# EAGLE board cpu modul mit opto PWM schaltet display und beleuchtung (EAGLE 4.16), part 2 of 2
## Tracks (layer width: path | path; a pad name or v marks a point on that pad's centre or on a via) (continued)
N$500  (via drill 0.5 pad 1.27)
  other vias: 50.32,1.9
N$501  (via drill 0.5 pad 1.27)
  other vias: 50.32,3.17
N$502  (via drill 0.5 pad 1.27)
  other vias: 49.05,1.9
N$503  (via drill 0.5 pad 1.27)
  other vias: 50.32,0.63
N$504  (via drill 0.5 pad 1.27)
  other vias: 51.59,1.9
N$506  (via drill 0.5 pad 1.27)
  other vias: 49.05,4.44
N$508  (via drill 0.5 pad 1.27)
  other vias: 33.81,24.76
N$509  (via drill 0.5 pad 1.27)
  other vias: 36.35,24.76
N$526  (via drill 0.5 pad 1.27)
  other vias: 5.87,14.6
N$527  (via drill 0.5 pad 1.27)
  other vias: 54.13,53.97
N$528  (via drill 0.5 pad 1.27)
  other vias: 54.13,55.24
N$529  (via drill 0.5 pad 1.27)
  other vias: 31.27,53.97
N$530  (via drill 0.5 pad 1.27)
  other vias: 31.27,55.24
N$531  (via drill 0.5 pad 1.27)
  other vias: 79.53,53.97
N$532  (via drill 0.5 pad 1.27)
  other vias: 82.07,53.97
N$533  (via drill 0.5 pad 1.27)
  other vias: 84.61,53.97
N$534  (via drill 0.5 pad 0.81)
  other vias: 0.79,57.78
N$535  (via drill 0.5 pad 0.81)
  other vias: 2.06,57.78
N$536  (via drill 0.5 pad 0.81)
  other vias: 3.33,57.78
N$537  (via drill 0.5 pad 0.81)
  other vias: 4.6,57.78
N$538  (via drill 0.5 pad 0.81)
  other vias: 5.87,57.78
N$539  (via drill 0.5 pad 0.81)
  other vias: 7.14,57.78
N$540  (via drill 0.5 pad 0.81)
  other vias: 8.41,57.78
N$541  (via drill 0.5 pad 0.81)
  other vias: 9.68,57.78
N$542  (via drill 0.5 pad 0.81)
  other vias: 10.95,57.78
N$543  (via drill 0.5 pad 0.81)
  other vias: 12.22,57.78
N$544  (via drill 0.5 pad 0.81)
  other vias: 13.49,57.78
N$545  (via drill 0.5 pad 0.81)
  other vias: 14.76,57.78
N$546  (via drill 0.5 pad 0.81)
  other vias: 16.03,57.78
N$547  (via drill 0.5 pad 0.81)
  other vias: 17.3,57.78
N$548  (via drill 0.5 pad 0.81)
  other vias: 18.57,57.78
N$549  (via drill 0.5 pad 0.81)
  other vias: 19.84,57.78
N$550  (via drill 0.5 pad 0.81)
  other vias: 21.11,57.78
N$551  (via drill 0.5 pad 0.81)
  other vias: 22.38,57.78
N$552  (via drill 0.5 pad 0.81)
  other vias: 23.65,57.78
N$553  (via drill 0.5 pad 0.81)
  other vias: 24.92,57.78
N$554  (via drill 0.5 pad 0.81)
  other vias: 26.19,57.78
N$555  (via drill 0.5 pad 0.81)
  other vias: 27.46,57.78
N$556  (via drill 0.5 pad 0.81)
  other vias: 28.73,57.78
N$557  (via drill 0.5 pad 0.81)
  other vias: 30,57.78
N$558  (via drill 0.5 pad 0.81)
  other vias: 31.27,57.78
N$559  (via drill 0.5 pad 0.81)
  other vias: 32.54,57.78
N$560  (via drill 0.5 pad 0.81)
  other vias: 33.81,57.78
N$561  (via drill 0.5 pad 0.81)
  other vias: 35.08,57.78
N$562  (via drill 0.5 pad 0.81)
  other vias: 36.35,57.78
N$563  (via drill 0.5 pad 0.81)
  other vias: 37.62,57.78
N$564  (via drill 0.5 pad 0.81)
  other vias: 40.16,57.78
N$565  (via drill 0.5 pad 0.81)
  other vias: 38.89,57.78
N$566  (via drill 0.5 pad 0.81)
  other vias: 41.43,57.78
N$567  (via drill 0.5 pad 0.81)
  other vias: 42.7,57.78
N$568  (via drill 0.5 pad 0.81)
  other vias: 43.97,57.78
N$569  (via drill 0.5 pad 0.81)
  other vias: 45.24,57.78
N$570  (via drill 0.5 pad 0.81)
  other vias: 46.51,57.78
N$571  (via drill 0.5 pad 0.81)
  other vias: 47.78,57.78
N$572  (via drill 0.5 pad 0.81)
  other vias: 49.05,57.78
N$573  (via drill 0.5 pad 0.81)
  other vias: 51.59,57.78
N$574  (via drill 0.5 pad 0.81)
  other vias: 50.32,57.78
N$575  (via drill 0.5 pad 0.81)
  other vias: 52.86,57.78
N$576  (via drill 0.5 pad 0.81)
  other vias: 54.13,57.78
N$577  (via drill 0.5 pad 0.81)
  other vias: 55.4,57.78
N$578  (via drill 0.5 pad 0.81)
  other vias: 56.67,57.78
N$579  (via drill 0.5 pad 0.81)
  other vias: 57.94,57.78
N$580  (via drill 0.5 pad 0.81)
  other vias: 59.21,57.78
N$581  (via drill 0.5 pad 0.81)
  other vias: 60.48,57.78
N$582  (via drill 0.5 pad 0.81)
  other vias: 61.75,57.78
N$583  (via drill 0.5 pad 0.81)
  other vias: 63.02,57.78
N$584  (via drill 0.5 pad 0.81)
  other vias: 64.29,57.78
N$585  (via drill 0.5 pad 0.81)
  other vias: 65.56,57.78
N$586  (via drill 0.5 pad 0.81)
  other vias: 66.83,57.78
N$587  (via drill 0.5 pad 0.81)
  other vias: 68.1,57.78
N$588  (via drill 0.5 pad 0.81)
  other vias: 69.37,57.78
N$589  (via drill 0.5 pad 0.81)
  other vias: 70.64,57.78
N$590  (via drill 0.5 pad 0.81)
  other vias: 71.91,57.78
N$591  (via drill 0.5 pad 0.81)
  other vias: 73.18,57.78
N$592  (via drill 0.5 pad 0.81)
  other vias: 74.45,57.78
N$593  (via drill 0.5 pad 0.81)
  other vias: 75.72,57.78
N$594  (via drill 0.5 pad 0.81)
  other vias: 76.99,57.78
N$595  (via drill 0.5 pad 0.81)
  other vias: 78.26,57.78
N$596  (via drill 0.5 pad 0.81)
  other vias: 79.53,57.78
N$597  (via drill 0.5 pad 0.81)
  other vias: 80.8,57.78
N$598  (via drill 0.5 pad 0.81)
  other vias: 82.07,57.78
N$599  (via drill 0.5 pad 0.81)
  other vias: 83.34,57.78
N$600  (via drill 0.5 pad 0.81)
  other vias: 84.61,57.78
N$601  (via drill 0.5 pad 0.81)
  other vias: 85.88,57.78
N$602  (via drill 0.5 pad 0.81)
  other vias: 87.15,57.78
N$603  (via drill 0.5 pad 1.27)
  other vias: 84.61,42.54
N$604  (via drill 0.5 pad 1.27)
  other vias: 84.61,45.08
N$605  (via drill 0.5 pad 1.27)
  other vias: 75.72,43.81
N$606  (via drill 0.5 pad 1.68)
  Bottom 0.406: 80.8,20.95 82.07,20.95 v83.34,20.95
N$607
  Bottom 0.406: 30,43.81 31.27,43.81
N$608
  Top 1.016: 56.77,61.7 56.77,66.52 56.57,66.72
N$609
  Top 1.016: 59.42,61.5 59.42,66.65
N$610
  Top 1.016: 62,61.5 62,66.45 61.79,66.65
N$611
  Top 1.016: 64.44,61.7 64.44,66.65 64.17,66.93
N$612
  Top 1.016: 66.81,61.5 66.81,66.86 66.75,66.93
N$613
  Top 1.016: 69.39,61.7 69.39,66.93
N$614
  Top 1.016: 71.9,61.5 71.9,66.65
N$615
  Top 1.016: 74.55,61.7 74.55,66.93
N$616
  Top 1.016: 77.13,61.7 77.13,66.65
N$617
  Top 1.016: 77.13,66.72 79.5,66.72
N$618  (via drill 0.5 pad 1.42)
  other vias: 56.75,64.08
N$619  (via drill 0.5 pad 1.42)
  other vias: 59.38,63.96
N$620  (via drill 0.5 pad 1.42)
  other vias: 61.85,63.96
N$621  (via drill 0.5 pad 1.42)
  other vias: 64.32,63.96
N$622  (via drill 0.5 pad 1.42)
  other vias: 66.68,63.96
N$623  (via drill 0.5 pad 1.42)
  other vias: 69.43,63.96
N$624  (via drill 0.5 pad 1.42)
  other vias: 51.69,63.96
N$625  (via drill 0.5 pad 1.42)
  other vias: 48.94,63.96
N$626  (via drill 0.5 pad 1.42)
  other vias: 46.47,63.96
N$627  (via drill 0.5 pad 1.42)
  other vias: 44,64.08
N$628  (via drill 0.5 pad 1.42)
  other vias: 41.41,64.08
N$629  (via drill 0.5 pad 1.42)
  other vias: 38.93,64.11
N$630  (via drill 0.5 pad 1.42)
  other vias: 36.3,64.23
N$631  (via drill 0.5 pad 1.42)
  other vias: 33.87,64.08
N$632  (via drill 0.5 pad 1.42)
  other vias: 31.24,64.11
N$633  (via drill 0.5 pad 1.42)
  other vias: 28.77,64.08
N$634  (via drill 0.5 pad 1.42)
  other vias: 5.77,63.96
N$635  (via drill 0.5 pad 1.42)
  other vias: 8.36,63.96
N$636  (via drill 0.5 pad 1.42)
  other vias: 10.99,63.96
N$637  (via drill 0.5 pad 1.42)
  other vias: 13.46,64.11
N$638  (via drill 0.5 pad 1.42)
  other vias: 15.94,64.08
N$639  (via drill 0.5 pad 1.42)
  other vias: 18.57,64.08
N$640  (via drill 0.5 pad 1.42)
  other vias: 21,64.08
N$641  (via drill 0.5 pad 1.42)
  other vias: 23.63,64.11
N$642  (via drill 0.5 pad 1.42)
  other vias: 26.22,64.08
N$643  (via drill 0.5 pad 1.42)
  other vias: 71.94,63.96
N$644  (via drill 0.5 pad 1.42)
  other vias: 74.57,63.96
N$645  (via drill 0.5 pad 1.42)
  other vias: 77.16,63.84
N$647  (via drill 0.5 pad 1.27)
  other vias: 69.41,49.33

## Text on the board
Top: PWM
Bottom: +5V | GND | GND | GND | IR | GND | GND | + | T | R | GND | Q0 | Q1 | Q0 | 5V+ out | IC2 | HI | GND | 1 | Display | DC IN | Taster | analog in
